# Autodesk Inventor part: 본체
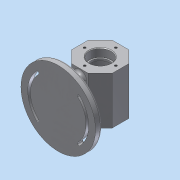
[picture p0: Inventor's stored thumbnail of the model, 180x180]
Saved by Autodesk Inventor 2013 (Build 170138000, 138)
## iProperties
Created: 2017-06
Part Number: 본체
Material: 알루미늄 6061
Document SubType Name: Modeling
Designer: dgall
Density: 2.71 g/cm^3
Mass: 562.296 g
Surface Area: 566.36 cm^2
Volume: 207.489 cm^3
Author: dgall
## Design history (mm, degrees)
sketch "스케치1"
  geometry: L1 (-30, 12.426)-(-12.426, 30); L2 (-12.426, 30)-(12.426, 30); L3 (12.426, 30)-(30, 12.426); L4 (30, 12.426)-(30, -12.426); L5 (30, -12.426)-(12.426, -30); L6 (12.426, -30)-(-12.426, -30); L7 (-12.426, -30)-(-30, -12.426); L8 (-30, -12.426)-(-30, 12.426); 2 further points
  constraints: 16 end point, 1 coincident, 1 vertical, 17 other
  dimensions: "d0" = 30 distance from line of L8 point (0, 0)
extrude "돌출1" new body sketch "스케치1" distance "d1" = 70; taper "d2" = 0 deg
sketch "스케치2"
  geometry: L1 (30, 70)-(12.426, 70) reference; L2 (12.426, 70)-(-12.426, 70) reference; L3 (12.426, 0)-(30, 0) reference; L4 (-12.426, 0)-(12.426, 0) reference; L5 (-30, 0)-(-12.426, 0) reference; L6 (-30, 0)-(-30, 70) reference; L7 (0, 0)-(0, 70); L8 (16, 58)-(14, 58); L9 (14, 58)-(14, 55); L10 (14, 55)-(22, 55); L11 (25, 52)-(25, 18); L12 (22, 15)-(14, 15); L13 (14, 15)-(14, 12); L14 (16, 70)-(16, 58); L15 (14, 12)-(16, 12); L16 (16, 12)-(16, 0); L17 (16, 70)-(30, 70); L18 (30, 0)-(16, 0); L19 (30, 0)-(30, 70); L20 (16, 70)-(0, 70); L21 (16, 0)-(0, 0); A1 r 3 centre (22, 52) between (25, 52) and (22, 55); A2 r 3 centre (22, 18) between (22, 15) and (25, 18)
  constraints: 30 end point, 4 collinear, 4 perpendicular, 4 point on circle, 4 point on line, 4 tangent, 3 parallel, 2 centre point, 2 vertical alignment, 1 equal radius, 1 midpoint
  dimensions: "d4" = 28 diameter of L9 L7; "d6" = 32 diameter of L14 L7; "d7" = 50 diameter of L11 L7; "d8" = 12 distance between parallel lines of L8 L2; "d10" = 40 distance between parallel lines of L12 L10; "d12" = 3 distance between parallel lines of L15 L12; "d13" = 3 radius of A1; "d14" = 60 diameter of L19 L7
revolve "회전1" sketch "스케치2" stored, may be unused: angle "d15" = 90 deg
node "작업 평면1"
sketch "스케치4"
  geometry: L1 (-30, 0)-(-30, 70) reference; L2 (30, 0)-(30, 70) reference; L3 (-12.426, 70)-(12.426, 70) reference; L4 (12.426, 0)-(-12.426, 0) reference; C1 r 55 at (0, 35); 2 further points
  constraints: 1 centre point, 1 midpoint, 1 vertical alignment
  dimensions: "d17" = 110 diameter of C1; "d18" = 35 distance from line of C1.centre L4
extrude "돌출2" join sketch "스케치4" distance "d19" = 10; taper "d20" = 0 deg
sketch "스케치6"
  geometry: L1 (30.406, 30.406)-(0, 0); L2 (0, 0)-(30.406, -30.406); L3 (0, 0)-(55, 0); A1 r 5 centre (30.406, 30.406) between (33.941, 33.941) and (26.87, 26.87); A2 r 48 centre (0, 0) between (33.941, -33.941) and (33.941, 33.941); A3 r 38 centre (0, 0) between (26.87, -26.87) and (26.87, 26.87); A4 r 5 centre (30.406, -30.406) between (26.87, -26.87) and (33.941, -33.941); A5 r 2 centre (30.406, 30.406) between (31.82, 31.82) and (28.991, 28.991); A6 r 41 centre (0, 0) between (28.991, -28.991) and (28.991, 28.991); A7 r 2 centre (30.406, -30.406) between (28.991, -28.991) and (31.82, -31.82); A8 r 45 centre (0, 0) between (31.82, -31.82) and (31.82, 31.82); 1 further point
  constraints: 16 point on circle, 8 centre point, 6 end point, 4 tangent, 2 coincident, 1 equal radius, 1 horizontal, 1 horizontal alignment, 1 perpendicular, 4 other
  dimensions: "d30" = 90 deg angle of L2 L1; "d31" = 45 deg angle of L3 L1; "d32" = 5 radius of A1; "d34" = 43 distance of L1.start L1.end; "d35" = 2 radius of A5
extrude "돌출3" cut sketch "스케치6" stored distance "d36" = 0; taper "d37" = 0 deg
extrude "돌출4" cut sketch "스케치6" distance "d38" = 3; taper "d39" = 0 deg
sketch "스케치7"
  geometry: L1 (-5, 24)-(-5, -24); L2 (5, -24)-(5, 24); A1 r 38 centre (0, 0) between (26.87, -26.87) and (26.87, 26.87) reference; A2 r 5 centre (0, -24) between (-5, -24) and (5, -24); A3 r 5 centre (0, 24) between (5, 24) and (-5, 24); 2 further points
  constraints: 4 end point, 4 point on circle, 4 tangent, 2 centre point, 2 vertical, 1 horizontal alignment, 1 midpoint, 1 vertical alignment
  dimensions: "d40" = 48 distance of A2.centre A3.centre; "d42" = 5 radius of A3
extrude "돌출5" join sketch "스케치7" stored distance "d43" = 0; taper "d44" = 0 deg
fillet "모깎기1" dims "d45" = 5
fillet "모깎기2" dims "d46" = 0.3
chamfer "모따기1" distance "d47" = 1; stored, may be unused: second distance "d48" = 2, angle "d49" = 45 deg
sketch "스케치8"
  geometry: C1 r 17 at (0, 0) reference; 1 further point
  constraints: 1 vertical alignment
  dimensions: "d50" = 23 distance of point (0, 23) C1.centre
hole "구멍1" sketch "스케치8" at (0, 23) diameter "d51" = 3.459; stored, may be unused: countersink angle "d55" = 90 deg, drill point angle "d57" = 118 deg; dims "d52" = 8, "d53" = 4, "d54" = 2, "d56" = 10
node "작업 평면2"
sketch "스케치9"
  geometry: L1 (42.426, 0)-(42.426, -70) reference; 2 further points
  constraints: 1 other
  dimensions: "d61" = 35 distance of point (12.426, -35) point (12.426, 0); "d62" = 30 distance from line of point (12.426, -35) L1
feature "엠보싱1" sketch "스케치9" dims "d63" = 0.5, "d64" = 0
sketch "스케치13"
  geometry: L1 (0, 0)-(-24.853, 0) reference; L2 (-42.426, 0)-(-42.426, 70) reference; C1 r 8 at (-12.426, 35); 1 further point
  constraints: 1 centre point
  dimensions: "d79" = 16 diameter of C1; "d80" = 35 distance from line of C1.centre L1; "d81" = 30 distance from line of C1.centre L2
extrude "돌출7" join sketch "스케치13" distance "d82" = 7; taper "d83" = 0 deg
sketch "스케치14"
  geometry: C1 r 8 at (0, 0) reference; 2 further points
  constraints: 1 coincident
hole "구멍3" sketch "스케치14" at (0, 0) diameter "d84" = 8; stored, may be unused: countersink angle "d88" = 90 deg, drill point angle "d90" = 118 deg; dims "d85" = 8, "d86" = 4, "d87" = 2, "d89" = 40
chamfer "모따기3" distance "d91" = 1; stored, may be unused: second distance "d92" = 2, angle "d93" = 45 deg
fillet "모깎기3" dims "d94" = 3
node "솔리드1"
mirror "대칭1"
pattern_circular "원형 패턴1" dims angle "d59" = 360 deg
mirror "대칭2"
other parameters: "d16" = -62, "d25" = 96
